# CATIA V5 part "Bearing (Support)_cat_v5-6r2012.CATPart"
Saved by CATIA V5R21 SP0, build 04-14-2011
Part number: Bearing (Support)
Bounding box of the stored display mesh (mm): x -270 to 10, y -39.842 to 39.842, z -34.808 to 139.842
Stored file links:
  D:\CATIA V5R21 E-RESOURCES\CATIA-V5R21\catia-v5r21-Tut\c16-catia-v5r21-tut\c16-catia-v5r21-tut02\Bearing (Support)_cat_v5r21.CATPart
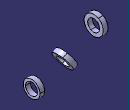
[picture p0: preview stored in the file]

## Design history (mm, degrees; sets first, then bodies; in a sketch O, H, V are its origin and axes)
Body1 (main body)
  Sketch1 on yz-plane, origin (0, 0, 0), H (0, 1, 0), V (0, 0, 1)
    circle A1 centre (0, 0) radius 25
    circle A2 centre (0, 0) radius 35
    radius A1 = 25
    radius A2 = 35
  Pad1: profile Sketch1, direction (1, 0, 0), length 10, mirrored extent
  Sketch2 on zx-plane, origin (0, 0, 0), H (-1, 0, 0), V (0, 0, 1)
    construction line L1 (0, 0) -> (60, 0)
    construction line L2 (60, 0) -> (194.1972, 77.4788)
    line L3 (107.5, 56.2917) -> (124.8205, 66.2917)
    line L4 (124.8205, 66.2917) -> (117.3205, 79.282)
    line L5 (117.3205, 79.282) -> (100, 69.282)
    point P6 (100, 69.282)
    line L6 (100, 69.282) -> (107.5, 56.2917)
    angle L2 L1 = 30
    distance L6 L4 = 20
    length L6 = 15
    distance L3 L2 = 25
    distance P6 V = 100
    length L1 = 60
    horizontal: L1 H
    perpendicularity: L4 L3
    parallelism: L5 L2, L6 L4
  Sketch3 on zx-plane, origin (0, 0, 0), H (-1, 0, 0), V (0, 0, 1)
    line L1 (60, 0) -> (221.9169, 93.4828)
    point P1 (60, 0)
    reference projected line E1 (107.5, 56.2917) -> (124.8205, 66.2917) from Sketch2.L3
    reference projected line E2 (107.5, 56.2917) -> (124.8205, 66.2917) from Sketch2.L3
    distance E2 L1 = 25
    coincidence: P1 H
    parallelism: L1 E1
  Shaft1: profile Sketch2, axis Sketch3.L1, angle 360
  Sketch4 on zx-plane, origin (0, 0, 0), H (-1, 0, 0), V (0, 0, 1)
    construction line L1 (188.3301, 100) -> (395.6544, 100)
    point P3 (260, 132.5)
    line L2 (270, 140) -> (270, 125)
    line L3 (270, 125) -> (250, 125)
    line L4 (250, 125) -> (250, 140)
    line L5 (250, 140) -> (270, 140)
    distance L1 H = 100
    length L5 = 20
    length L4 = 15
    distance L1 L3 = 25
    distance L4 V = 250
    horizontal: L1 H, L3 H, L5 H
    vertical: L2 V, L4 V
    equidistance: L2 L4 P3, L3 L5 P3
  Sketch5 on zx-plane, origin (0, 0, 0), H (-1, 0, 0), V (0, 0, 1)
    line L1 (210.3804, 100) -> (348.9415, 100)
    reference projected line E1 (250, 125) -> (270, 125) from Sketch4.L3
    distance L1 E1 = 25
    horizontal: L1 H
  Shaft2: profile Sketch4, axis Sketch5.L1, angle 360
